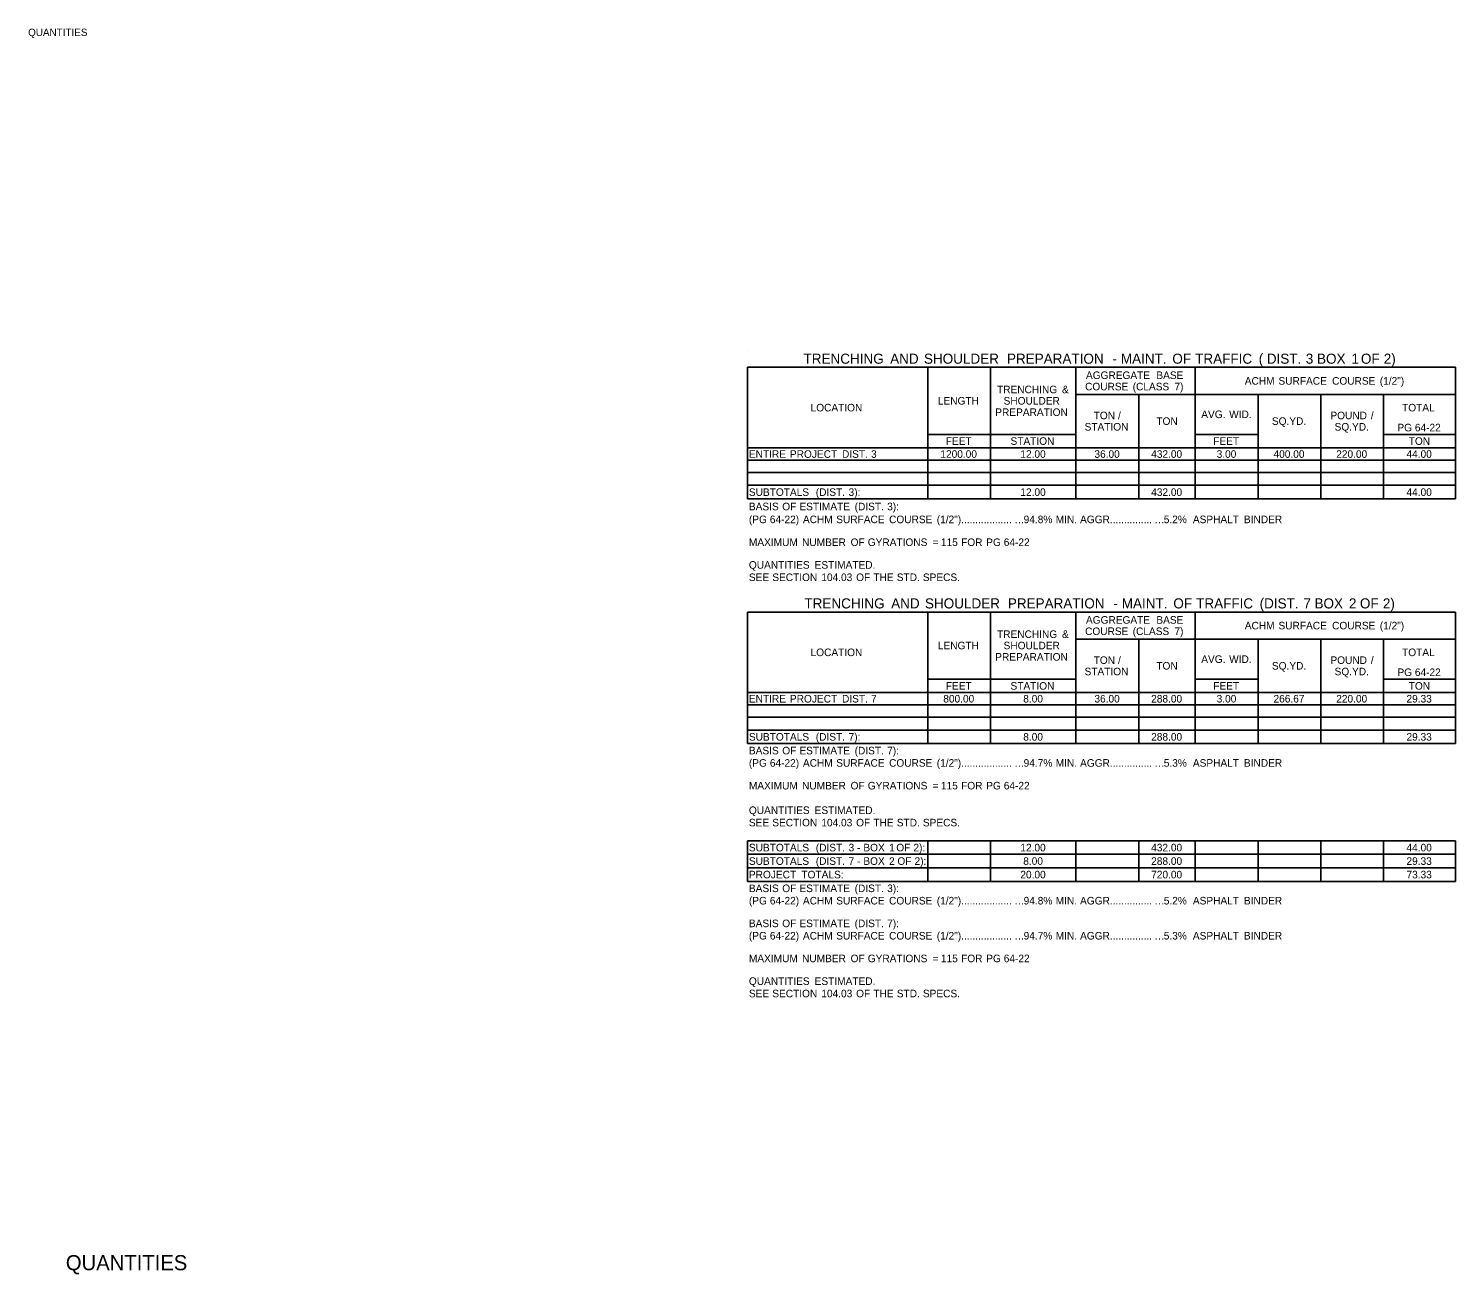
# Model space of a CAD drawing. Extents: x 544478 to 1930787, y -1948294 to 596640.
# Drawn here: x 555164 to 556295, y -1947044 to -1946056 of the extents above; entities that cross this region are included whole.
import ezdxf

# ---------------------------------------------------------------- set-up
doc = ezdxf.new("R2010")
doc.units = 0
for name, color, linetype in [('Default', 7, 'Continuous'), ('R_Border', 7, 'Continuous'), ('R_Border Prem', 7, 'Continuous')]:
    doc.layers.add(name, color=color, linetype=linetype)

msp = doc.modelspace()

# ---------------------------------------------------------------- linework, layer by layer
at = {"layer": 'Default'}
for p, q in [((555733.6, -1946311.4), (555733.6, -1946311.4)), ((555733.6, -1946325), (556294.7, -1946325)), ((555733.6, -1946429.4), (555733.6, -1946325)), ((555876.4, -1946429.4), (555876.4, -1946325)), ((555926.2, -1946429.4), (555926.2, -1946325)), ((555993.9, -1946429.4), (555993.9, -1946325)), ((556088.5, -1946429.4), (556088.5, -1946325)), ((556294.7, -1946429.4), (556294.7, -1946325)), ((555993.9, -1946346.5), (556294.7, -1946346.5)), ((556043.7, -1946429.4), (556043.7, -1946346.5)), ((556138.2, -1946429.4), (556138.2, -1946346.5)), ((556188, -1946429.4), (556188, -1946346.5)), ((556237.7, -1946429.4), (556237.7, -1946346.5)), ((555733.6, -1946388.9), (555993.9, -1946388.9)), ((555876.4, -1946378.2), (555993.9, -1946378.2)), ((555876.4, -1946429.4), (555876.4, -1946388.9)), ((555926.2, -1946418.6), (555926.2, -1946378.2)), ((555993.9, -1946388.9), (556138.2, -1946388.9)), ((555993.9, -1946418.6), (555993.9, -1946388.9)), ((556043.7, -1946418.6), (556043.7, -1946388.9)), ((556088.5, -1946378.2), (556138.2, -1946378.2)), ((556088.5, -1946388.9), (556088.5, -1946378.2)), ((556138.2, -1946418.6), (556138.2, -1946378.2)), ((556138.2, -1946388.9), (556294.7, -1946388.9)), ((556188, -1946418.6), (556188, -1946388.9)), ((556237.7, -1946378.2), (556294.7, -1946378.2)), ((555733.6, -1946398.6), (556294.7, -1946398.6)), ((555733.6, -1946408.4), (556294.7, -1946408.4)), ((555733.6, -1946418.6), (556294.7, -1946418.6)), ((555733.6, -1946418.6), (556294.7, -1946418.6)), ((555733.6, -1946429.4), (556294.7, -1946429.4)), ((555733.6, -1946519.1), (556294.7, -1946519.1)), ((555733.6, -1946623.4), (555733.6, -1946519.1)), ((555876.4, -1946623.4), (555876.4, -1946519.1)), ((555926.2, -1946623.4), (555926.2, -1946519.1)), ((555993.9, -1946623.4), (555993.9, -1946519.1)), ((556088.5, -1946623.4), (556088.5, -1946519.1)), ((556294.7, -1946623.4), (556294.7, -1946519.1)), ((555993.9, -1946540.5), (556294.7, -1946540.5)), ((556043.7, -1946623.4), (556043.7, -1946540.5)), ((556138.2, -1946623.4), (556138.2, -1946540.5)), ((556188, -1946623.4), (556188, -1946540.5)), ((556237.7, -1946623.4), (556237.7, -1946540.5)), ((555876.4, -1946572.2), (555993.9, -1946572.2)), ((555926.2, -1946612.7), (555926.2, -1946572.2)), ((556088.5, -1946572.2), (556138.2, -1946572.2)), ((556088.5, -1946582.9), (556088.5, -1946572.2)), ((556138.2, -1946612.7), (556138.2, -1946572.2)), ((556237.7, -1946572.2), (556294.7, -1946572.2)), ((555733.6, -1946582.9), (555993.9, -1946582.9)), ((555733.6, -1946592.7), (556294.7, -1946592.7)), ((555876.4, -1946623.4), (555876.4, -1946582.9)), ((555993.9, -1946582.9), (556138.2, -1946582.9)), ((555993.9, -1946612.7), (555993.9, -1946582.9)), ((556043.7, -1946612.7), (556043.7, -1946582.9)), ((556138.2, -1946582.9), (556294.7, -1946582.9)), ((556188, -1946612.7), (556188, -1946582.9)), ((555733.6, -1946602.4), (556294.7, -1946602.4)), ((555733.6, -1946612.7), (556294.7, -1946612.7)), ((555733.6, -1946612.7), (556294.7, -1946612.7)), ((555733.6, -1946623.4), (556294.7, -1946623.4)), ((555733.6, -1946700.4), (556294.7, -1946700.4)), ((555733.6, -1946700.4), (556294.7, -1946700.4)), ((555733.6, -1946732.6), (555733.6, -1946700.4)), ((555876.4, -1946732.6), (555876.4, -1946700.4)), ((555876.4, -1946732.6), (555876.4, -1946700.4)), ((555926.2, -1946732.6), (555926.2, -1946700.4)), ((555993.9, -1946732.6), (555993.9, -1946700.4)), ((556043.7, -1946732.6), (556043.7, -1946700.4)), ((556088.5, -1946732.6), (556088.5, -1946700.4)), ((556138.2, -1946732.6), (556138.2, -1946700.4)), ((556188, -1946732.6), (556188, -1946700.4)), ((556237.7, -1946732.6), (556237.7, -1946700.4)), ((556294.7, -1946732.6), (556294.7, -1946700.4)), ((555733.6, -1946711.1), (556294.7, -1946711.1)), ((555733.6, -1946721.9), (556294.7, -1946721.9)), ((555733.6, -1946732.6), (556294.7, -1946732.6))]:
    msp.add_line(p, q, dxfattribs=at)

# ---------------------------------------------------------------- texts
for s, height, p in [('TRENCHING', 8, (555777.9, -1946322.2)), (' AND', 8, (555843.6, -1946322.2)), (' SHOULDER', 8, (555870.4, -1946322.2)), (' PREPARATION', 8, (555936.2, -1946322.2)), (' -', 8, (556019.7, -1946322.2)), (' MAINT.', 8, (556026.5, -1946322.2)), (' OF', 8, (556067.3, -1946322.2)), (' TRAFFIC', 8, (556085.4, -1946322.2)), (' (', 8, (556135.8, -1946322.2)), (' DIST.', 8, (556142.2, -1946322.2)), (' 3', 8, (556173.1, -1946322.2)), (' BOX', 8, (556182, -1946322.2)), (' 1', 8, (556209.3, -1946322.2)), (' OF', 8, (556216.8, -1946322.2)), (' 2)', 8, (556234.9, -1946322.2)), ('AGGREGATE', 6, (556001.8, -1946334.3)), (' BASE', 6, (556055.4, -1946334.3)), (' (1/2")', 6, (556232.5, -1946338.8)), ('TRENCHING', 6, (555931.3, -1946345.6)), (' &', 6, (555980.6, -1946345.6)), ('COURSE', 6, (556001.1, -1946343.3)), (' (CLASS', 6, (556036.6, -1946343.3)), (' 7)', 6, (556069.7, -1946343.3)), ('ACHM', 6, (556127.7, -1946338.8)), (' SURFACE', 6, (556152.2, -1946338.8)), (' COURSE', 6, (556194.7, -1946338.8)), ('LOCATION', 6, (555783.5, -1946360)), ('LENGTH', 6, (555884.4, -1946354.6)), ('SHOULDER', 6, (555936.5, -1946354.6)), ('TOTAL', 6, (556252.4, -1946360)), ('PREPARATION', 6, (555929.9, -1946363.6)), ('TON', 6, (556007.9, -1946366.2)), (' /', 6, (556025, -1946366.2)), ('TON', 6, (556057.6, -1946370.7)), ('AVG.', 6, (556093.2, -1946365.3)), (' WID.', 6, (556113.1, -1946365.3)), ('SQ.YD.', 6, (556149.2, -1946370.7)), ('POUND', 6, (556195.6, -1946366.2)), (' /', 6, (556225.4, -1946366.2)), ('STATION', 6, (556000.7, -1946375.2)), ('SQ.YD.', 6, (556198.9, -1946375.2)), ('PG', 6, (556248.7, -1946375.8)), (' 64-22', 6, (556260.3, -1946375.8)), ('FEET', 6, (555890.7, -1946386.5)), ('STATION', 6, (555942, -1946386.5)), ('FEET', 6, (556102.7, -1946386.5)), ('TON', 6, (556257.7, -1946386.5)), ('ENTIRE', 6, (555734.6, -1946396.8)), (' PROJECT', 6, (555764.9, -1946396.8)), (' DIST.', 6, (555806.2, -1946396.8)), (' 3', 6, (555829.2, -1946396.8)), ('1200.00', 6, (555886.4, -1946396.8)), ('12.00', 6, (555949.8, -1946396.8)), ('36.00', 6, (556008.5, -1946396.8)), ('432.00', 6, (556053.5, -1946396.8)), ('3.00', 6, (556105.4, -1946396.8)), ('400.00', 6, (556150.5, -1946396.8)), ('220.00', 6, (556200.2, -1946396.8)), ('44.00', 6, (556255.9, -1946396.8)), ('SUBTOTALS', 6, (555734.6, -1946427)), (' (DIST.', 6, (555785.4, -1946427)), (' 3):', 6, (555811.4, -1946427)), ('12.00', 6, (555949.8, -1946427)), ('432.00', 6, (556053.5, -1946427)), ('44.00', 6, (556255.9, -1946427)), ('BASIS', 6, (555734.6, -1946438.4)), (' OF', 6, (555758.8, -1946438.4)), (' ESTIMATE', 6, (555772.4, -1946438.4)), (' (DIST.', 6, (555816.2, -1946438.4)), (' 3):', 6, (555842, -1946438.4)), ('(PG', 6, (555734.6, -1946448.6)), (' 64-22)', 6, (555749, -1946448.6)), (' ACHM', 6, (555775.2, -1946448.6)), (' SURFACE', 6, (555801.6, -1946448.6)), (' COURSE', 6, (555843.5, -1946448.6)), (' (1/2")..................', 6, (555881.3, -1946448.6)), ('94.8%', 6, (555952.4, -1946448.6)), (' MIN.', 6, (555975.6, -1946448.6)), (' AGGR...............', 6, (555994.9, -1946448.6)), ('5.2%', 6, (556063.5, -1946448.6)), ('  ASPHALT', 6, (556082.1, -1946448.6)), (' BINDER', 6, (556124.8, -1946448.6)), ('…', 6, (555945, -1946448.6)), ('…', 6, (556056.1, -1946448.6)), ('MAXIMUM', 6, (555734.6, -1946466.7)), (' NUMBER', 6, (555774.5, -1946466.7)), (' OF', 6, (555813, -1946466.7)), (' GYRATIONS', 6, (555826.6, -1946466.7)), (' =', 6, (555877.9, -1946466.7)), (' 115', 6, (555884.6, -1946466.7)), (' FOR', 6, (555900.6, -1946466.7)), (' PG', 6, (555920.5, -1946466.7)), (' 64-22', 6, (555934.4, -1946466.7)), ('QUANTITIES', 6, (555734.6, -1946484.7)), (' ESTIMATED.', 6, (555784.5, -1946484.7)), ('SEE', 6, (555734.6, -1946494.5)), (' SECTION', 6, (555750.9, -1946494.5)), (' 104.03', 6, (555789.8, -1946494.5)), (' OF', 6, (555817.4, -1946494.5)), (' THE', 6, (555831, -1946494.5)), (' STD.', 6, (555849.6, -1946494.5)), (' SPECS.', 6, (555870.3, -1946494.5)), ('TRENCHING', 8, (555778.6, -1946516.2)), (' AND', 8, (555844.4, -1946516.2)), (' SHOULDER', 8, (555871.2, -1946516.2)), (' PREPARATION', 8, (555936.9, -1946516.2)), (' -', 8, (556020.5, -1946516.2)), (' MAINT.', 8, (556027.2, -1946516.2)), (' OF', 8, (556068.1, -1946516.2)), (' TRAFFIC', 8, (556086.2, -1946516.2)), (' (DIST.', 8, (556136.5, -1946516.2)), (' 7', 8, (556171.2, -1946516.2)), (' BOX', 8, (556180, -1946516.2)), (' 2', 8, (556207.3, -1946516.2)), (' OF', 8, (556216, -1946516.2)), (' 2)', 8, (556234.2, -1946516.2)), ('AGGREGATE', 6, (556001.8, -1946528.3)), (' BASE', 6, (556055.4, -1946528.3)), ('TRENCHING', 6, (555931.3, -1946539.6)), (' &', 6, (555980.6, -1946539.6)), ('COURSE', 6, (556001.1, -1946537.3)), (' (CLASS', 6, (556036.6, -1946537.3)), (' 7)', 6, (556069.7, -1946537.3)), ('ACHM', 6, (556127.7, -1946532.8)), (' SURFACE', 6, (556152.2, -1946532.8)), (' COURSE', 6, (556194.7, -1946532.8)), (' (1/2")', 6, (556232.5, -1946532.8)), ('LENGTH', 6, (555884.4, -1946548.6)), ('SHOULDER', 6, (555936.5, -1946548.6)), ('LOCATION', 6, (555783.5, -1946554)), ('PREPARATION', 6, (555929.9, -1946557.6)), ('TON', 6, (556007.9, -1946560.2)), (' /', 6, (556025, -1946560.2)), ('TON', 6, (556057.6, -1946564.7)), ('AVG.', 6, (556093.2, -1946559.4)), (' WID.', 6, (556113.1, -1946559.4)), ('SQ.YD.', 6, (556149.2, -1946564.7)), ('POUND', 6, (556195.6, -1946560.2)), (' /', 6, (556225.4, -1946560.2)), ('TOTAL', 6, (556252.4, -1946554)), ('STATION', 6, (556000.7, -1946569.2)), ('SQ.YD.', 6, (556198.9, -1946569.2)), ('PG', 6, (556248.7, -1946569.8)), (' 64-22', 6, (556260.3, -1946569.8)), ('FEET', 6, (555890.7, -1946580.6)), ('STATION', 6, (555942, -1946580.6)), ('FEET', 6, (556102.7, -1946580.6)), ('TON', 6, (556257.7, -1946580.6)), ('ENTIRE', 6, (555734.6, -1946590.8)), (' PROJECT', 6, (555764.9, -1946590.8)), (' DIST.', 6, (555806.2, -1946590.8)), (' 7', 6, (555829.2, -1946590.8)), ('800.00', 6, (555888.7, -1946590.8)), ('8.00', 6, (555952.1, -1946590.8)), ('36.00', 6, (556008.5, -1946590.8)), ('288.00', 6, (556053.5, -1946590.8)), ('3.00', 6, (556105.4, -1946590.8)), ('266.67', 6, (556150.5, -1946590.8)), ('220.00', 6, (556200.2, -1946590.8)), ('29.33', 6, (556255.9, -1946590.8)), ('SUBTOTALS', 6, (555734.6, -1946621)), (' (DIST.', 6, (555785.4, -1946621)), (' 7):', 6, (555811.4, -1946621)), ('8.00', 6, (555952.1, -1946621)), ('288.00', 6, (556053.5, -1946621)), ('29.33', 6, (556255.9, -1946621)), ('BASIS', 6, (555734.6, -1946631.9)), (' OF', 6, (555758.8, -1946631.9)), (' ESTIMATE', 6, (555772.4, -1946631.9)), (' (DIST.', 6, (555816.2, -1946631.9)), (' 7):', 6, (555842, -1946631.9)), ('(PG', 6, (555734.6, -1946641.7)), (' 64-22)', 6, (555749, -1946641.7)), (' ACHM', 6, (555775.2, -1946641.7)), (' SURFACE', 6, (555801.6, -1946641.7)), (' COURSE', 6, (555843.5, -1946641.7)), (' (1/2")..................', 6, (555881.3, -1946641.7)), ('94.7%', 6, (555952.4, -1946641.7)), (' MIN.', 6, (555975.6, -1946641.7)), (' AGGR...............', 6, (555994.9, -1946641.7)), ('5.3%', 6, (556063.5, -1946641.7)), ('  ASPHALT', 6, (556082.1, -1946641.7)), (' BINDER', 6, (556124.8, -1946641.7)), ('…', 6, (555945, -1946641.7)), ('…', 6, (556056.1, -1946641.7)), ('MAXIMUM', 6, (555734.6, -1946659.7)), (' NUMBER', 6, (555774.5, -1946659.7)), (' OF', 6, (555813, -1946659.7)), (' GYRATIONS', 6, (555826.6, -1946659.7)), (' =', 6, (555877.9, -1946659.7)), (' 115', 6, (555884.6, -1946659.7)), (' FOR', 6, (555900.6, -1946659.7)), (' PG', 6, (555920.5, -1946659.7)), (' 64-22', 6, (555934.4, -1946659.7)), ('SEE', 6, (555734.6, -1946689)), ('QUANTITIES', 6, (555734.6, -1946679.2)), (' SECTION', 6, (555750.9, -1946689)), (' ESTIMATED.', 6, (555784.5, -1946679.2)), (' 104.03', 6, (555789.8, -1946689)), (' OF', 6, (555817.4, -1946689)), (' THE', 6, (555831, -1946689)), (' STD.', 6, (555849.6, -1946689)), (' SPECS.', 6, (555870.3, -1946689)), ('SUBTOTALS', 6, (555734.6, -1946708.8)), (' (DIST.', 6, (555785.4, -1946708.8)), (' 3', 6, (555811.4, -1946708.8)), (' BOX', 6, (555823.1, -1946708.8)), (' 1', 6, (555843.5, -1946708.8)), (' OF', 6, (555849.2, -1946708.8)), (' 2):', 6, (555862.8, -1946708.8)), ('12.00', 6, (555949.8, -1946708.8)), ('432.00', 6, (556053.5, -1946708.8)), ('44.00', 6, (556255.9, -1946708.8)), ('SUBTOTALS', 6, (555734.6, -1946719.5)), (' (DIST.', 6, (555785.4, -1946719.5)), (' 7', 6, (555811.4, -1946719.5)), (' -', 6, (555818, -1946708.8)), (' -', 6, (555818, -1946719.5)), (' BOX', 6, (555823.1, -1946719.5)), (' 2', 6, (555843.5, -1946719.5)), (' OF', 6, (555850.1, -1946719.5)), (' 2):', 6, (555863.7, -1946719.5)), ('8.00', 6, (555952.1, -1946719.5)), ('288.00', 6, (556053.5, -1946719.5)), ('29.33', 6, (556255.9, -1946719.5)), ('PROJECT', 6, (555734.6, -1946730.2)), (' TOTALS:', 6, (555774, -1946730.2)), ('20.00', 6, (555949.8, -1946730.2)), ('720.00', 6, (556053.5, -1946730.2)), ('73.33', 6, (556255.9, -1946730.2)), ('BASIS', 6, (555734.6, -1946741.1)), (' OF', 6, (555758.8, -1946741.1)), (' ESTIMATE', 6, (555772.4, -1946741.1)), (' (DIST.', 6, (555816.2, -1946741.1)), (' 3):', 6, (555842, -1946741.1)), ('(PG', 6, (555734.6, -1946750.9)), (' 64-22)', 6, (555749, -1946750.9)), (' ACHM', 6, (555775.2, -1946750.9)), (' SURFACE', 6, (555801.6, -1946750.9)), (' COURSE', 6, (555843.5, -1946750.9)), (' (1/2")..................', 6, (555881.3, -1946750.9)), ('…', 6, (555945, -1946750.9)), ('94.8%', 6, (555952.4, -1946750.9)), (' MIN.', 6, (555975.6, -1946750.9)), (' AGGR...............', 6, (555994.9, -1946750.9)), ('…', 6, (556056.1, -1946750.9)), ('5.2%', 6, (556063.5, -1946750.9)), ('  ASPHALT', 6, (556082.1, -1946750.9)), (' BINDER', 6, (556124.8, -1946750.9)), ('(PG', 6, (555734.6, -1946778.7)), ('BASIS', 6, (555734.6, -1946768.9)), (' 64-22)', 6, (555749, -1946778.7)), (' OF', 6, (555758.8, -1946768.9)), (' ESTIMATE', 6, (555772.4, -1946768.9)), (' ACHM', 6, (555775.2, -1946778.7)), (' SURFACE', 6, (555801.6, -1946778.7)), (' (DIST.', 6, (555816.2, -1946768.9)), (' 7):', 6, (555842, -1946768.9)), (' COURSE', 6, (555843.5, -1946778.7)), (' (1/2")..................', 6, (555881.3, -1946778.7)), ('94.7%', 6, (555952.4, -1946778.7)), (' MIN.', 6, (555975.6, -1946778.7)), (' AGGR...............', 6, (555994.9, -1946778.7)), ('5.3%', 6, (556063.5, -1946778.7)), ('  ASPHALT', 6, (556082.1, -1946778.7)), (' BINDER', 6, (556124.8, -1946778.7)), ('…', 6, (555945, -1946778.7)), ('…', 6, (556056.1, -1946778.7)), ('MAXIMUM', 6, (555734.6, -1946796.7)), (' NUMBER', 6, (555774.5, -1946796.7)), (' OF', 6, (555813, -1946796.7)), (' GYRATIONS', 6, (555826.6, -1946796.7)), (' =', 6, (555877.9, -1946796.7)), (' 115', 6, (555884.6, -1946796.7)), (' FOR', 6, (555900.6, -1946796.7)), (' PG', 6, (555920.5, -1946796.7)), (' 64-22', 6, (555934.4, -1946796.7)), ('SEE', 6, (555734.6, -1946824.5)), ('QUANTITIES', 6, (555734.6, -1946814.7)), (' SECTION', 6, (555750.9, -1946824.5)), (' ESTIMATED.', 6, (555784.5, -1946814.7)), (' 104.03', 6, (555789.8, -1946824.5)), (' OF', 6, (555817.4, -1946824.5)), (' THE', 6, (555831, -1946824.5)), (' STD.', 6, (555849.6, -1946824.5)), (' SPECS.', 6, (555870.3, -1946824.5))]:
    msp.add_text(s, height=height, dxfattribs=at).set_placement(p)
at = {"layer": 'R_Border'}
msp.add_text('QUANTITIES', height=12, rotation=360, dxfattribs=at).set_placement((555193.1, -1947040.9))
at = {"layer": 'R_Border Prem'}
msp.add_text('QUANTITIES', height=5.86, rotation=360, dxfattribs=at).set_placement((555163.2, -1946062.4))

doc.saveas('drawing.dxf')
